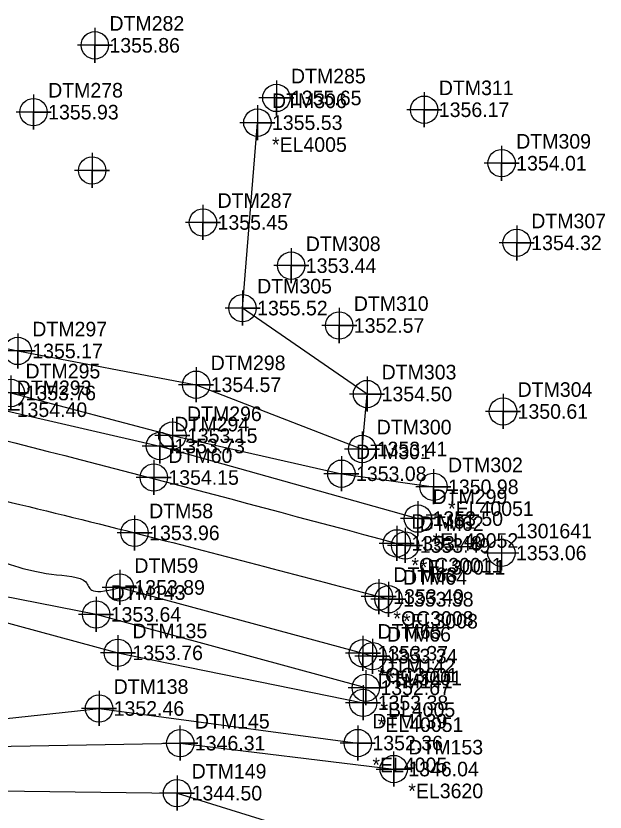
# Model space of a CAD drawing. Extents: x 1251905 to 1252853, y 859795 to 860170.
# Drawn here: x 1252152.2 to 1252253.1, y 860021.6 to 860158 of the extents above; entities that cross this region are included whole.
import ezdxf

# ---------------------------------------------------------------- set-up
doc = ezdxf.new("R2010")
doc.units = 0
for name, color, linetype in [('Cogo Default Point CELL', 7, 'Continuous'), ('COGO Default Point Elevation', 7, 'Continuous'), ('COGO Default Point Number', 7, 'Continuous'), ('Exist DTM Breakline', 7, 'Continuous'), ('Exist DTM Breakline Cogo Comment', 7, 'Continuous'), ('Exist DTM Breakline Cogo Elevation', 7, 'Continuous'), ('Exist DTM Breakline Cogo Number', 7, 'Continuous'), ('Exist DTM Breakline Cogo Point CELL', 7, 'Continuous'), ('Exist DTM Breakline Underwater', 7, 'Continuous'), ('Exist DTM Breakline Underwater Cogo Elevation', 7, 'Continuous'), ('Exist DTM Breakline Underwater Cogo Number', 7, 'Continuous'), ('Exist DTM Breakline Underwater Cogo Point CELL', 7, 'Continuous'), ('Exist DTM Crownline', 7, 'Continuous'), ('Exist DTM Crownline Cogo Comment', 7, 'Continuous'), ('Exist DTM Crownline Cogo Elevation', 7, 'Continuous'), ('Exist DTM Crownline Cogo Number', 7, 'Continuous'), ('Exist DTM Crownline Cogo Point CELL', 7, 'Continuous'), ('Exist DTM Regular Point CELL', 7, 'Continuous'), ('Exist DTM Regular Point Cogo Elevation', 7, 'Continuous'), ('Exist DTM Regular Point Cogo Number', 7, 'Continuous'), ('Exist Hydro Stream or Body of Water', 7, 'Continuous'), ('Exist Hydro Stream or Body of Water Cogo Comment', 7, 'Continuous'), ('Exist Hydro Stream or Body of Water Cogo Elevation', 7, 'Continuous'), ('Exist Hydro Stream or Body of Water Cogo Number', 7, 'Continuous'), ('Exist Hydro Stream or Body of Water Cogo Point CELL', 7, 'Continuous'), ('Exist Roads EOP', 7, 'Continuous'), ('Exist Roads EOP Cogo Comment', 7, 'Continuous'), ('Exist Roads EOP Cogo Elevation', 7, 'Continuous'), ('Exist Roads EOP Cogo Number', 7, 'Continuous'), ('Exist Roads EOP Cogo Point CELL', 7, 'Continuous'), ('Exist Vegetation Tree Cogo Elevation', 7, 'Continuous'), ('Exist Vegetation Tree Cogo Number', 7, 'Continuous')]:
    doc.layers.add(name, color=color, linetype=linetype)

msp = doc.modelspace()

# ---------------------------------------------------------------- linework, layer by layer
at = {"layer": 'Cogo Default Point CELL'}
for points in [[(1252235.379, 860068.9959999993), (1252235.379, 860065.9959999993)], [(1252232.379, 860065.9959999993), (1252235.379, 860065.9959999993)], [(1252235.379, 860065.9959999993), (1252238.379, 860065.9959999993)], [(1252235.379, 860065.9959999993), (1252235.379, 860062.9959999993)]]:
    msp.add_lwpolyline(points, dxfattribs=at)
msp.add_circle((1252235.379, 860065.9959999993), 2.344041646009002, dxfattribs=at)
at = {"layer": 'Exist DTM Breakline'}
for points in [[(1251958.1300000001, 860094.898), (1251998.718, 860091.9280000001), (1252030.771, 860103.262), (1252049.551, 860107.507), (1252087.7920000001, 860120.138), (1252107.828, 860109.909), (1252152.49, 860100.596), (1252183.064, 860094.812), (1252211.5150000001, 860083.799), (1252212.351, 860093.22), (1252191.02, 860107.9450000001), (1252193.563, 860139.71)], [(1252049.493, 860105.996), (1252086.378, 860112.482), (1252107.399, 860104.568), (1252151.324, 860093.395), (1252178.994, 860086.087), (1252207.96, 860079.566), (1252223.7380000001, 860077.321)], [(1252042.065, 860097.328), (1252080.061, 860103.224), (1252106.299, 860098.116), (1252149.813, 860090.533), (1252176.834, 860084.313), (1252221.078, 860071.872)], [(1252212.143, 860042.894), (1252165.922, 860055.456), (1252123.408, 860063.782), (1252098.156, 860066.464), (1252072.182, 860063.615), (1252055.654, 860055.275)], [(1252061.299, 860052.806), (1252088.425, 860042.6780000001), (1252111.564, 860045.6680000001), (1252135.233, 860058.213), (1252169.648, 860048.881), (1252211.681, 860040.318)], [(1252046.935, 860042.529), (1252048.558, 860037.478), (1252071.192, 860034.305), (1252085.116, 860031.692), (1252110.305, 860033.296), (1252166.428, 860039.344), (1252210.773, 860033.4230000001)]]:
    msp.add_lwpolyline(points, dxfattribs=at)
at = {"layer": 'Exist DTM Breakline Cogo Point CELL'}
for points in [[(1252193.563, 860142.7099999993), (1252193.563, 860136.7099999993), (1252193.563, 860139.7099999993), (1252196.563, 860139.7099999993), (1252190.563, 860139.7099999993)], [(1252191.02, 860110.9449999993), (1252191.02, 860104.9449999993), (1252191.02, 860107.9449999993), (1252194.02, 860107.9449999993), (1252188.02, 860107.9449999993)], [(1252152.49, 860103.5959999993), (1252152.49, 860097.5959999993), (1252152.49, 860100.5959999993), (1252155.49, 860100.5959999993), (1252149.49, 860100.5959999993)], [(1252183.064, 860097.8119999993), (1252183.064, 860091.8119999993), (1252183.064, 860094.8119999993), (1252186.064, 860094.8119999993), (1252180.064, 860094.8119999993)], [(1252151.324, 860096.3949999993), (1252151.324, 860090.3949999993), (1252151.324, 860093.3949999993), (1252154.324, 860093.3949999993), (1252148.324, 860093.3949999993)], [(1252212.351, 860096.2199999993), (1252212.351, 860090.2199999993), (1252212.351, 860093.2199999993), (1252215.351, 860093.2199999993), (1252209.351, 860093.2199999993)], [(1252149.813, 860093.5329999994), (1252149.813, 860087.5329999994), (1252149.813, 860090.5329999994), (1252152.813, 860090.5329999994), (1252146.813, 860090.5329999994)], [(1252178.994, 860089.0869999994), (1252178.994, 860083.0869999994), (1252178.994, 860086.0869999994), (1252181.994, 860086.0869999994), (1252175.994, 860086.0869999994)], [(1252176.834, 860087.3129999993), (1252176.834, 860081.3129999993), (1252176.834, 860084.3129999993), (1252179.834, 860084.3129999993), (1252173.834, 860084.3129999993)], [(1252211.5150000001, 860086.7989999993), (1252211.5150000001, 860080.7989999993), (1252211.5150000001, 860083.7989999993), (1252214.5150000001, 860083.7989999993), (1252208.5150000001, 860083.7989999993)], [(1252207.96, 860082.5659999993), (1252207.96, 860076.5659999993), (1252207.96, 860079.5659999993), (1252210.96, 860079.5659999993), (1252204.96, 860079.5659999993)], [(1252223.7380000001, 860080.3209999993), (1252223.7380000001, 860074.3209999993), (1252223.7380000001, 860077.3209999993), (1252226.7380000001, 860077.3209999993), (1252220.7380000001, 860077.3209999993)], [(1252221.078, 860074.8719999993), (1252221.078, 860068.8719999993), (1252221.078, 860071.8719999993), (1252224.078, 860071.8719999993), (1252218.078, 860071.8719999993)], [(1252165.922, 860058.4559999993), (1252165.922, 860052.4559999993), (1252165.922, 860055.4559999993), (1252168.922, 860055.4559999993), (1252162.922, 860055.4559999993)], [(1252169.648, 860051.8809999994), (1252169.648, 860045.8809999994), (1252169.648, 860048.8809999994), (1252172.648, 860048.8809999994), (1252166.648, 860048.8809999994)], [(1252212.143, 860045.8939999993), (1252212.143, 860039.8939999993), (1252212.143, 860042.8939999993), (1252215.143, 860042.8939999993), (1252209.143, 860042.8939999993)], [(1252211.681, 860043.3179999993), (1252211.681, 860037.3179999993), (1252211.681, 860040.3179999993), (1252214.681, 860040.3179999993), (1252208.681, 860040.3179999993)], [(1252166.428, 860042.3439999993), (1252166.428, 860036.3439999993), (1252166.428, 860039.3439999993), (1252169.428, 860039.3439999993), (1252163.428, 860039.3439999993)], [(1252210.773, 860036.4229999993), (1252210.773, 860030.4229999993), (1252210.773, 860033.4229999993), (1252213.773, 860033.4229999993), (1252207.773, 860033.4229999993)]]:
    msp.add_lwpolyline(points, dxfattribs=at)
for centre in [(1252193.563, 860139.7099999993), (1252191.02, 860107.9449999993), (1252152.49, 860100.5959999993), (1252183.064, 860094.8119999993), (1252151.324, 860093.3949999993), (1252212.351, 860093.2199999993), (1252178.994, 860086.0869999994), (1252176.834, 860084.3129999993), (1252211.5150000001, 860083.7989999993), (1252207.96, 860079.5659999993), (1252223.7380000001, 860077.3209999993), (1252221.078, 860071.8719999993), (1252165.922, 860055.4559999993), (1252169.648, 860048.8809999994), (1252212.143, 860042.8939999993), (1252166.428, 860039.3439999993), (1252211.681, 860040.3179999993), (1252210.773, 860033.4229999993)]:
    msp.add_circle(centre, 2.344041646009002, dxfattribs=at)
at = {"layer": 'Exist DTM Breakline Underwater'}
msp.add_lwpolyline([(1251927.42, 860049.6630000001), (1251960.607, 860043.4280000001), (1251991.544, 860038.5430000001), (1252023.095, 860021.002), (1252051.108, 860015.006), (1252097.4440000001, 860018.35), (1252136.124, 860025.415), (1252179.795, 860024.836), (1252209.0420000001, 860015.729)], dxfattribs=at)
at = {"layer": 'Exist DTM Breakline Underwater Cogo Point CELL'}
msp.add_lwpolyline([(1252179.795, 860027.8359999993), (1252179.795, 860021.8359999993), (1252179.795, 860024.8359999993), (1252182.795, 860024.8359999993), (1252176.795, 860024.8359999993)], dxfattribs=at)
msp.add_circle((1252179.795, 860024.8359999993), 2.344041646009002, dxfattribs=at)
at = {"layer": 'Exist DTM Crownline'}
msp.add_line((1252214.359, 860058.511), (1252216.022, 860058.052), dxfattribs=at)
msp.add_spline([(1252036.243, 860048.539), (1252039.0760000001, 860060.231), (1252047.752, 860070.723), (1252058.446, 860077.2170000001), (1252075.17, 860082.787), (1252097.364, 860084.644), (1252123.933, 860080.792), (1252172.517, 860069.427), (1252214.359, 860058.511)], degree=3, dxfattribs=at)
at = {"layer": 'Exist DTM Crownline Cogo Point CELL'}
for points in [[(1252172.517, 860072.4269999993), (1252172.517, 860066.4269999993), (1252172.517, 860069.4269999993), (1252175.517, 860069.4269999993), (1252169.517, 860069.4269999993)], [(1252214.359, 860061.5109999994), (1252214.359, 860055.5109999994), (1252214.359, 860058.5109999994), (1252217.359, 860058.5109999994), (1252211.359, 860058.5109999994)], [(1252216.022, 860061.0519999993), (1252216.022, 860055.0519999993), (1252216.022, 860058.0519999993), (1252219.022, 860058.0519999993), (1252213.022, 860058.0519999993)]]:
    msp.add_lwpolyline(points, dxfattribs=at)
for centre in [(1252172.517, 860069.4269999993), (1252214.359, 860058.5109999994), (1252216.022, 860058.0519999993)]:
    msp.add_circle(centre, 2.344041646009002, dxfattribs=at)
at = {"layer": 'Exist DTM Regular Point CELL'}
for points in [[(1252165.707, 860155.9619999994), (1252165.707, 860149.9619999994), (1252165.707, 860152.9619999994), (1252168.707, 860152.9619999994), (1252162.707, 860152.9619999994)], [(1252196.814, 860146.9459999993), (1252196.814, 860140.9459999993), (1252196.814, 860143.9459999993), (1252199.814, 860143.9459999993), (1252193.814, 860143.9459999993)], [(1252155.206, 860144.5159999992), (1252155.206, 860138.5159999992), (1252155.206, 860141.5159999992), (1252158.206, 860141.5159999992), (1252152.206, 860141.5159999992)], [(1252222.158, 860144.9289999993), (1252222.158, 860138.9289999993), (1252222.158, 860141.9289999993), (1252225.158, 860141.9289999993), (1252219.158, 860141.9289999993)], [(1252235.42, 860135.7629999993), (1252235.42, 860129.7629999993), (1252235.42, 860132.7629999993), (1252238.42, 860132.7629999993), (1252232.42, 860132.7629999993)], [(1252165.2328934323, 860134.526959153), (1252165.2328934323, 860128.526959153), (1252165.2328934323, 860131.526959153), (1252168.2328934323, 860131.526959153), (1252162.2328934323, 860131.526959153)], [(1252184.236, 860125.6159999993), (1252184.236, 860119.6159999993), (1252184.236, 860122.6159999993), (1252187.236, 860122.6159999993), (1252181.236, 860122.6159999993)], [(1252237.9980000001, 860122.1169999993), (1252237.9980000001, 860116.1169999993), (1252237.9980000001, 860119.1169999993), (1252240.9980000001, 860119.1169999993), (1252234.9980000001, 860119.1169999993)], [(1252199.362, 860118.2119999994), (1252199.362, 860112.2119999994), (1252199.362, 860115.2119999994), (1252202.362, 860115.2119999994), (1252196.362, 860115.2119999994)], [(1252207.589, 860107.9599999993), (1252207.589, 860101.9599999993), (1252207.589, 860104.9599999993), (1252210.589, 860104.9599999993), (1252204.589, 860104.9599999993)], [(1252235.655, 860093.2319999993), (1252235.655, 860087.2319999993), (1252235.655, 860090.2319999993), (1252238.655, 860090.2319999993), (1252232.655, 860090.2319999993)]]:
    msp.add_lwpolyline(points, dxfattribs=at)
for centre in [(1252165.707, 860152.9619999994), (1252196.814, 860143.9459999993), (1252155.206, 860141.5159999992), (1252222.158, 860141.9289999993), (1252235.42, 860132.7629999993), (1252165.2328934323, 860131.526959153), (1252184.236, 860122.6159999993), (1252237.9980000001, 860119.1169999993), (1252199.362, 860115.2119999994), (1252207.589, 860104.9599999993), (1252235.655, 860090.2319999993)]:
    msp.add_circle(centre, 2.344041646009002, dxfattribs=at)
at = {"layer": 'Exist Hydro Stream or Body of Water'}
msp.add_lwpolyline([(1252097.617, 860027.411), (1252135.268, 860032.617), (1252180.354, 860033.405), (1252216.928, 860028.966)], dxfattribs=at)
at = {"layer": 'Exist Hydro Stream or Body of Water Cogo Point CELL'}
for points in [[(1252177.354, 860033.4049999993), (1252183.354, 860033.4049999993), (1252180.354, 860033.4049999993), (1252180.354, 860030.4049999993), (1252180.354, 860036.4049999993)], [(1252213.928, 860028.9659999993), (1252219.928, 860028.9659999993), (1252216.928, 860028.9659999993), (1252216.928, 860025.9659999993), (1252216.928, 860031.9659999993)]]:
    msp.add_lwpolyline(points, dxfattribs=at)
for centre in [(1252180.354, 860033.4049999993), (1252216.928, 860028.9659999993)]:
    msp.add_circle(centre, 2.344041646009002, dxfattribs=at)
at = {"layer": 'Exist Roads EOP'}
for p, q in [((1252217.458, 860067.633), (1252218.885, 860067.273)), ((1252211.6560000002, 860048.796), (1252213.278, 860048.3030000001))]:
    msp.add_line(p, q, dxfattribs=at)
msp.add_lwpolyline([(1252169.98, 860060.0819999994), (1252211.656, 860048.7959999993)], dxfattribs=at)
for points in [[(1252098.205, 860095.441), (1252105.1614077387, 860094.6882099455), (1252112.220556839, 860093.7969971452), (1252119.2789275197, 860092.6450357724), (1252126.233, 860091.11), (1252217.458, 860067.633)], [(1252045.803, 860048.12), (1252049.087, 860055.674), (1252050.2153975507, 860057.6515921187), (1252051.6839917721, 860059.4129647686), (1252053.3720901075, 860061.0363550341), (1252055.159, 860062.6), (1252057.0142268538, 860064.1325732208), (1252058.9250323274, 860065.5135143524), (1252060.9378216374, 860066.7191983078), (1252063.099, 860067.726), (1252069.836107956, 860069.8939456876), (1252076.731, 860071.145), (1252086.7906137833, 860072.1203664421), (1252096.85, 860072.458), (1252103.1642067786, 860072.2657761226), (1252109.4781924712, 860071.8459595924), (1252115.7920819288, 860071.306163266), (1252122.106, 860070.7540000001), (1252128.211654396, 860069.9862457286), (1252134.2921622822, 860068.7856334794), (1252146.3586576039, 860065.6279820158), (1252158.2673241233, 860062.3653395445), (1252164.150546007, 860061.0334885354), (1252169.98, 860060.082), (1252169.9800000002, 860060.082)]]:
    msp.add_spline(points, degree=3, dxfattribs=at)
at = {"layer": 'Exist Roads EOP Cogo Point CELL'}
for points in [[(1252175.8090000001, 860081.9189999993), (1252175.8090000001, 860075.9189999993), (1252175.8090000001, 860078.9189999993), (1252178.8090000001, 860078.9189999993), (1252172.8090000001, 860078.9189999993)], [(1252217.458, 860070.6329999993), (1252217.458, 860064.6329999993), (1252217.458, 860067.6329999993), (1252220.458, 860067.6329999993), (1252214.458, 860067.6329999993)], [(1252218.885, 860070.2729999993), (1252218.885, 860064.2729999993), (1252218.885, 860067.2729999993), (1252221.885, 860067.2729999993), (1252215.885, 860067.2729999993)], [(1252169.98, 860063.0819999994), (1252169.98, 860057.0819999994), (1252169.98, 860060.0819999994), (1252172.98, 860060.0819999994), (1252166.98, 860060.0819999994)], [(1252211.656, 860051.7959999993), (1252211.656, 860045.7959999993), (1252211.656, 860048.7959999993), (1252214.656, 860048.7959999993), (1252208.656, 860048.7959999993)], [(1252213.278, 860051.3029999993), (1252213.278, 860045.3029999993), (1252213.278, 860048.3029999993), (1252216.278, 860048.3029999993), (1252210.278, 860048.3029999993)]]:
    msp.add_lwpolyline(points, dxfattribs=at)
for centre in [(1252175.8090000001, 860078.9189999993), (1252217.458, 860067.6329999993), (1252218.885, 860067.2729999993), (1252169.98, 860060.0819999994), (1252211.656, 860048.7959999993), (1252213.278, 860048.3029999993)]:
    msp.add_circle(centre, 2.344041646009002, dxfattribs=at)

# ---------------------------------------------------------------- texts
at = {"layer": 'COGO Default Point Elevation'}
msp.add_text('1353.06', height=2.5, dxfattribs=at).set_placement((1252237.879, 860064.746))
at = {"layer": 'COGO Default Point Number'}
msp.add_text('1301641', height=2.5, dxfattribs=at).set_placement((1252237.879, 860068.496))
at = {"layer": 'Exist DTM Breakline Cogo Comment'}
for s, p in [('*EL4005', (1252196.063, 860134.71)), ('*EL40051', (1252226.2380000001, 860072.321)), ('*EL40052', (1252223.578, 860066.872)), ('*BL4005', (1252214.643, 860037.894)), ('*EL40051', (1252214.181, 860035.318)), ('*EL4005', (1252213.273, 860028.4230000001))]:
    msp.add_text(s, height=2.5, dxfattribs=at).set_placement(p)
at = {"layer": 'Exist DTM Breakline Cogo Elevation'}
for s, p in [('1355.53', (1252196.063, 860138.46)), ('1355.52', (1252193.52, 860106.6950000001)), ('1355.17', (1252154.99, 860099.346)), ('1354.57', (1252185.564, 860093.562)), ('1353.76', (1252153.824, 860092.145)), ('1354.50', (1252214.851, 860091.97)), ('1354.40', (1252152.313, 860089.283)), ('1353.15', (1252181.494, 860084.837)), ('1353.73', (1252179.334, 860083.063)), ('1353.41', (1252214.0150000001, 860082.549)), ('1353.08', (1252210.46, 860078.316)), ('1350.98', (1252226.2380000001, 860076.071)), ('1353.50', (1252223.578, 860070.622)), ('1353.64', (1252168.422, 860054.206)), ('1353.76', (1252172.148, 860047.631)), ('1352.67', (1252214.643, 860041.644)), ('1353.38', (1252214.181, 860039.068)), ('1352.46', (1252168.928, 860038.094)), ('1352.36', (1252213.273, 860032.1730000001))]:
    msp.add_text(s, height=2.5, dxfattribs=at).set_placement(p)
at = {"layer": 'Exist DTM Breakline Cogo Number'}
for s, p in [('DTM306', (1252196.063, 860142.21)), ('DTM305', (1252193.52, 860110.4450000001)), ('DTM297', (1252154.99, 860103.096)), ('DTM298', (1252185.564, 860097.312)), ('DTM295', (1252153.824, 860095.895)), ('DTM303', (1252214.851, 860095.72)), ('DTM293', (1252152.313, 860093.033)), ('DTM296', (1252181.494, 860088.587)), ('DTM294', (1252179.334, 860086.813)), ('DTM300', (1252214.0150000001, 860086.299)), ('DTM301', (1252210.46, 860082.066)), ('DTM302', (1252226.2380000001, 860079.821)), ('DTM299', (1252223.578, 860074.372)), ('DTM143', (1252168.422, 860057.956)), ('DTM135', (1252172.148, 860051.381)), ('DTM142', (1252214.643, 860045.394)), ('DTM138', (1252168.928, 860041.844)), ('DTM141', (1252214.181, 860042.818)), ('DTM139', (1252213.273, 860035.9230000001))]:
    msp.add_text(s, height=2.5, dxfattribs=at).set_placement(p)
at = {"layer": 'Exist DTM Breakline Underwater Cogo Elevation'}
msp.add_text('1344.50', height=2.5, dxfattribs=at).set_placement((1252182.295, 860023.586))
at = {"layer": 'Exist DTM Breakline Underwater Cogo Number'}
msp.add_text('DTM149', height=2.5, dxfattribs=at).set_placement((1252182.295, 860027.336))
at = {"layer": 'Exist DTM Crownline Cogo Comment'}
for s, p in [('*OC3008', (1252216.859, 860053.511)), ('*EL3008', (1252218.522, 860053.052))]:
    msp.add_text(s, height=2.5, dxfattribs=at).set_placement(p)
at = {"layer": 'Exist DTM Crownline Cogo Elevation'}
for s, p in [('1353.96', (1252175.017, 860068.177)), ('1353.40', (1252216.859, 860057.261)), ('1353.38', (1252218.522, 860056.802))]:
    msp.add_text(s, height=2.5, dxfattribs=at).set_placement(p)
at = {"layer": 'Exist DTM Crownline Cogo Number'}
for s, p in [('DTM58', (1252175.017, 860071.927)), ('DTM63', (1252216.859, 860061.011)), ('DTM64', (1252218.522, 860060.552))]:
    msp.add_text(s, height=2.5, dxfattribs=at).set_placement(p)
at = {"layer": 'Exist DTM Regular Point Cogo Elevation'}
for s, p in [('1355.86', (1252168.207, 860151.712)), ('1355.65', (1252199.314, 860142.696)), ('1356.17', (1252224.658, 860140.679)), ('1354.01', (1252237.92, 860131.513)), ('1355.45', (1252186.736, 860121.366)), ('1354.32', (1252240.4980000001, 860117.867)), ('1353.44', (1252201.862, 860113.962)), ('1352.57', (1252210.089, 860103.71)), ('1350.61', (1252238.155, 860088.982))]:
    msp.add_text(s, height=2.5, dxfattribs=at).set_placement(p)
at = {"layer": 'Exist DTM Regular Point Cogo Number'}
for s, p in [('DTM282', (1252168.207, 860155.462)), ('DTM285', (1252199.314, 860146.446)), ('DTM311', (1252224.658, 860144.429)), ('DTM309', (1252237.92, 860135.263)), ('DTM287', (1252186.736, 860125.116)), ('DTM307', (1252240.4980000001, 860121.617)), ('DTM308', (1252201.862, 860117.712)), ('DTM310', (1252210.089, 860107.46)), ('DTM304', (1252238.155, 860092.732))]:
    msp.add_text(s, height=2.5, dxfattribs=at).set_placement(p)
at = {"layer": 'Exist Hydro Stream or Body of Water Cogo Comment'}
msp.add_text('*EL3620', height=2.5, dxfattribs=at).set_placement((1252219.428, 860023.966))
at = {"layer": 'Exist Hydro Stream or Body of Water Cogo Elevation'}
for s, p in [('1346.31', (1252182.854, 860032.155)), ('1346.04', (1252219.428, 860027.716))]:
    msp.add_text(s, height=2.5, dxfattribs=at).set_placement(p)
at = {"layer": 'Exist Hydro Stream or Body of Water Cogo Number'}
for s, p in [('DTM145', (1252182.854, 860035.905)), ('DTM153', (1252219.428, 860031.466))]:
    msp.add_text(s, height=2.5, dxfattribs=at).set_placement(p)
at = {"layer": 'Exist Roads EOP Cogo Comment'}
for s, p in [('*OC30011', (1252219.958, 860062.633)), ('*EL30011', (1252221.385, 860062.273)), ('*OC3001', (1252214.156, 860043.796)), ('*EL3001', (1252215.778, 860043.3030000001))]:
    msp.add_text(s, height=2.5, dxfattribs=at).set_placement(p)
at = {"layer": 'Exist Roads EOP Cogo Elevation'}
for s, p in [('1354.15', (1252178.3090000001, 860077.669)), ('1353.48', (1252219.958, 860066.383)), ('1353.49', (1252221.385, 860066.023)), ('1353.89', (1252172.48, 860058.832)), ('1353.37', (1252214.156, 860047.546)), ('1353.34', (1252215.778, 860047.0530000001))]:
    msp.add_text(s, height=2.5, dxfattribs=at).set_placement(p)
at = {"layer": 'Exist Roads EOP Cogo Number'}
for s, p in [('DTM60', (1252178.3090000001, 860081.419)), ('DTM61', (1252219.958, 860070.133)), ('DTM62', (1252221.385, 860069.773)), ('DTM59', (1252172.48, 860062.582)), ('DTM65', (1252214.156, 860051.296)), ('DTM66', (1252215.778, 860050.8030000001))]:
    msp.add_text(s, height=2.5, dxfattribs=at).set_placement(p)
at = {"layer": 'Exist Vegetation Tree Cogo Elevation'}
msp.add_text('1355.93', height=2.5, dxfattribs=at).set_placement((1252157.706, 860140.2660000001))
at = {"layer": 'Exist Vegetation Tree Cogo Number'}
msp.add_text('DTM278', height=2.5, dxfattribs=at).set_placement((1252157.706, 860144.0160000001))

doc.saveas('drawing.dxf')
